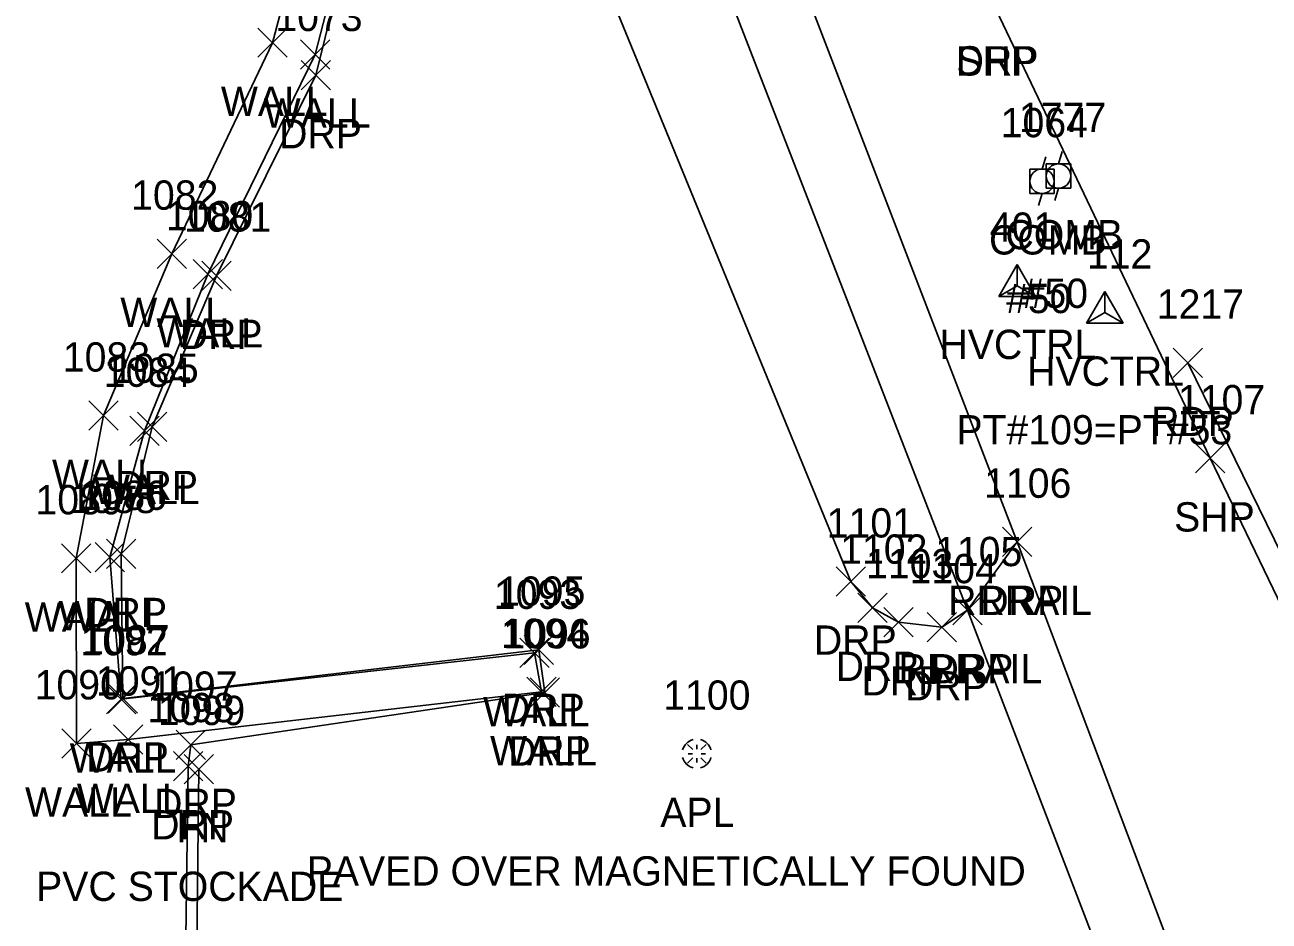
# Model space of a CAD drawing. Extents: x 1635588 to 1637550, y 621583 to 623638.
# Drawn here: x 1636394.7 to 1636479.5, y 623053.3 to 623114.4 of the extents above; entities that cross this region are included whole.
import ezdxf

# ---------------------------------------------------------------- set-up
doc = ezdxf.new("R2010")
doc.units = 0
for name, color, linetype in [('C_A', 7, 'Continuous'), ('C_C', 7, 'Continuous'), ('C_I', 7, 'Continuous'), ('CPSM', 7, 'Continuous'), ('Default', 7, 'Continuous'), ('L_A', 7, 'Continuous'), ('L_C', 7, 'Continuous'), ('L_I', 7, 'Continuous'), ('L_TIC', 7, 'Continuous'), ('LFNC', 7, 'Continuous'), ('LW', 7, 'Continuous'), ('M_A', 7, 'Continuous'), ('M_C', 7, 'Continuous'), ('M_I', 7, 'Continuous'), ('P_A', 7, 'Continuous'), ('P_I', 7, 'Continuous'), ('P_TIC', 7, 'Continuous'), ('PET', 7, 'Continuous'), ('PSP', 7, 'Continuous'), ('R_A', 7, 'Continuous'), ('R_I', 7, 'Continuous'), ('R_TIC', 7, 'Continuous'), ('RDP', 7, 'Continuous'), ('RR', 7, 'Continuous'), ('U_A', 7, 'Continuous'), ('U_C', 7, 'Continuous'), ('U_I', 7, 'Continuous'), ('UP', 7, 'Continuous')]:
    doc.layers.add(name, color=color, linetype=linetype)

msp = doc.modelspace()

# ---------------------------------------------------------------- linework, layer by layer
at = {"layer": 'CPSM'}
for p, q in [((1636461.112, 623095.915), (1636462.362, 623098.081)), ((1636463.612, 623095.915), (1636462.362, 623098.081)), ((1636462.362, 623096.637), (1636462.362, 623098.081)), ((1636461.112, 623095.915), (1636462.362, 623096.637)), ((1636462.362, 623096.637), (1636462.362, 623096.637)), ((1636462.362, 623096.637), (1636463.612, 623095.915)), ((1636467.085, 623094.088), (1636468.335, 623096.253)), ((1636469.585, 623094.088), (1636468.335, 623096.253)), ((1636468.335, 623094.809), (1636468.335, 623096.253)), ((1636461.112, 623095.915), (1636463.612, 623095.915)), ((1636467.085, 623094.088), (1636468.335, 623094.809)), ((1636468.335, 623094.809), (1636468.335, 623094.809)), ((1636468.335, 623094.809), (1636469.585, 623094.088)), ((1636467.085, 623094.088), (1636469.585, 623094.088))]:
    msp.add_line(p, q, dxfattribs=at)
at = {"layer": 'Default'}
for p, q in [((1636439.871, 623065.342), (1636440.225, 623064.989)), ((1636440.508, 623065.006), (1636440.508, 623065.306)), ((1636440.79, 623064.989), (1636441.144, 623065.342)), ((1636439.871, 623064.07), (1636440.225, 623064.423)), ((1636439.908, 623064.706), (1636440.208, 623064.706)), ((1636440.508, 623064.106), (1636440.508, 623064.406)), ((1636440.79, 623064.423), (1636441.144, 623064.07)), ((1636440.808, 623064.706), (1636441.108, 623064.706))]:
    msp.add_line(p, q, dxfattribs=at)
for start, end in [(105, 165), (15, 75), (195, 255), (285, 345)]:
    msp.add_arc((1636440.508, 623064.706), 1, start, end, dxfattribs=at)
at = {"layer": 'L_TIC'}
for points in [[(1636410.564, 623112.225), (1636412.564, 623114.225)], [(1636412.564, 623112.225), (1636410.564, 623114.225)], [(1636413.484, 623111.423), (1636415.484, 623113.423)], [(1636415.484, 623111.423), (1636413.484, 623113.423)], [(1636403.702, 623097.825), (1636405.702, 623099.825)], [(1636405.702, 623097.825), (1636403.702, 623099.825)], [(1636406.16, 623096.425), (1636408.16, 623098.425)], [(1636408.16, 623096.425), (1636406.16, 623098.425)], [(1636399.045, 623086.778), (1636401.045, 623088.778)], [(1636401.045, 623086.778), (1636399.045, 623088.778)], [(1636401.84, 623085.739), (1636403.84, 623087.739)], [(1636403.84, 623085.739), (1636401.84, 623087.739)], [(1636397.187, 623077.038), (1636399.187, 623079.038)], [(1636399.187, 623077.038), (1636397.187, 623079.038)], [(1636399.489, 623077.124), (1636401.489, 623079.124)], [(1636401.489, 623077.124), (1636399.489, 623079.124)], [(1636428.437, 623070.584), (1636430.437, 623072.584)], [(1636430.437, 623070.584), (1636428.437, 623072.584)], [(1636428.919, 623067.918), (1636430.919, 623069.918)], [(1636430.919, 623067.918), (1636428.919, 623069.918)], [(1636428.919, 623067.918), (1636430.919, 623069.918)], [(1636430.919, 623067.918), (1636428.919, 623069.918)], [(1636400.251, 623067.418), (1636402.251, 623069.418)], [(1636402.251, 623067.418), (1636400.251, 623069.418)], [(1636400.736, 623064.668), (1636402.736, 623066.668)], [(1636402.736, 623064.668), (1636400.736, 623066.668)], [(1636397.21, 623064.41), (1636399.21, 623066.41)], [(1636399.21, 623064.41), (1636397.21, 623066.41)], [(1636405.539, 623062.658), (1636407.539, 623064.658)], [(1636407.539, 623062.658), (1636405.539, 623064.658)]]:
    msp.add_lwpolyline(points, dxfattribs=at)
at = {"layer": 'LFNC'}
msp.add_lwpolyline([(1636406.539, 623063.658), (1636405.234, 622947.043)], dxfattribs=at)
at = {"layer": 'LW'}
for points in [[(1636420.537, 623148.867), (1636418.032, 623137.549), (1636411.564, 623113.225), (1636404.702, 623098.825), (1636400.045, 623087.778), (1636398.187, 623078.038), (1636398.21, 623065.41), (1636401.736, 623065.668), (1636429.919, 623068.918)], [(1636420.537, 623148.867), (1636423.272, 623148.269), (1636420.807, 623136.928), (1636414.484, 623112.423), (1636407.16, 623097.425), (1636402.84, 623086.739), (1636400.489, 623078.124), (1636401.251, 623068.418), (1636429.437, 623071.584), (1636429.919, 623068.918)]]:
    msp.add_lwpolyline(points, dxfattribs=at)
at = {"layer": 'P_TIC'}
for points in [[(1636472.997, 623090.384), (1636474.997, 623092.384)], [(1636474.997, 623090.384), (1636472.997, 623092.384)], [(1636474.52, 623083.866), (1636476.52, 623085.866)], [(1636476.52, 623083.866), (1636474.52, 623085.866)]]:
    msp.add_lwpolyline(points, dxfattribs=at)
at = {"layer": 'PET'}
msp.add_lwpolyline([(1636496.543, 623045.303), (1636473.997, 623091.384)], dxfattribs=at)
at = {"layer": 'PSP'}
msp.add_lwpolyline([(1636412.613, 623220.066), (1636436.6, 623167.303), (1636456.229, 623125.071), (1636460.67, 623115.983), (1636475.52, 623084.866), (1636494.511, 623045.421), (1636524.158, 622986.515), (1636530.738, 622972.235), (1636554.067, 622925.303), (1636577.184, 622886.299), (1636601.725, 622847.414), (1636613.464, 622830.092), (1636645.381, 622782.471), (1636700.606, 622698.856), (1636734.281, 622648.07), (1636752.122, 622619.298), (1636752.456, 622616.814), (1636755.34, 622613.417), (1636810.04, 622534.387), (1636855.631, 622465.664), (1636874.755, 622437.489), (1636904.151, 622393.551)], dxfattribs=at)
at = {"layer": 'R_TIC'}
for points in [[(1636413.536, 623110.016), (1636415.536, 623112.016)], [(1636415.536, 623110.016), (1636413.536, 623112.016)], [(1636406.752, 623096.325), (1636408.752, 623098.325)], [(1636408.752, 623096.325), (1636406.752, 623098.325)], [(1636402.358, 623086.008), (1636404.358, 623088.008)], [(1636404.358, 623086.008), (1636402.358, 623088.008)], [(1636461.356, 623078.168), (1636463.356, 623080.168)], [(1636463.356, 623078.168), (1636461.356, 623080.168)], [(1636461.356, 623078.168), (1636463.356, 623080.168)], [(1636463.356, 623078.168), (1636461.356, 623080.168)], [(1636400.247, 623077.342), (1636402.247, 623079.342)], [(1636402.247, 623077.342), (1636400.247, 623079.342)], [(1636450.004, 623075.459), (1636452.004, 623077.459)], [(1636452.004, 623075.459), (1636450.004, 623077.459)], [(1636451.488, 623073.67), (1636453.488, 623075.67)], [(1636453.488, 623073.67), (1636451.488, 623075.67)], [(1636457.958, 623073.504), (1636459.958, 623075.504)], [(1636459.958, 623073.504), (1636457.958, 623075.504)], [(1636457.958, 623073.504), (1636459.958, 623075.504)], [(1636459.958, 623073.504), (1636457.958, 623075.504)], [(1636453.253, 623072.679), (1636455.253, 623074.679)], [(1636455.253, 623072.679), (1636453.253, 623074.679)], [(1636456.222, 623072.339), (1636458.222, 623074.339)], [(1636458.222, 623072.339), (1636456.222, 623074.339)], [(1636428.728, 623070.801), (1636430.728, 623072.801)], [(1636430.728, 623070.801), (1636428.728, 623072.801)], [(1636429.144, 623067.888), (1636431.144, 623069.888)], [(1636431.144, 623067.888), (1636429.144, 623069.888)], [(1636400.371, 623067.481), (1636402.371, 623069.481)], [(1636402.371, 623067.481), (1636400.371, 623069.481)], [(1636405.011, 623064.317), (1636407.011, 623066.317)], [(1636407.011, 623064.317), (1636405.011, 623066.317)], [(1636404.812, 623062.856), (1636406.812, 623064.856)], [(1636406.812, 623062.856), (1636404.812, 623064.856)]]:
    msp.add_lwpolyline(points, dxfattribs=at)
at = {"layer": 'RDP'}
for points in [[(1636426.436, 623136.427), (1636420.977, 623137.097), (1636414.536, 623111.016), (1636407.752, 623097.325), (1636403.358, 623087.008), (1636401.247, 623078.342), (1636401.371, 623068.481), (1636429.728, 623071.801), (1636430.144, 623068.888), (1636406.011, 623065.317), (1636405.812, 623063.856), (1636404.224, 622946.579), (1636428.105, 622945.115), (1636429.145, 622942.892), (1636426.113, 622934.054), (1636419.919, 622924.842), (1636405.506, 622913.035), (1636421.178, 622869.939), (1636453.551, 622783.031), (1636469.62, 622787.524)], [(1636426.436, 623136.427), (1636451.004, 623076.459), (1636452.488, 623074.67), (1636454.253, 623073.679), (1636457.222, 623073.339), (1636458.958, 623074.504), (1636462.356, 623079.168)]]:
    msp.add_lwpolyline(points, dxfattribs=at)
at = {"layer": 'RR'}
for points in [[(1636406.427, 623208.621), (1636424.648, 623171.195), (1636442.267, 623131.473), (1636462.356, 623079.168), (1636475.096, 623045.335), (1636499.502, 622979.797), (1636509.409, 622950.551), (1636516.072, 622929.712), (1636530.199, 622882.108), (1636568.929, 622740.93), (1636580.618, 622697.816)], [(1636401.965, 623205.775), (1636420.488, 623168.355), (1636437.726, 623129.252), (1636458.958, 623074.504), (1636470.759, 623043.725), (1636495.269, 622977.34), (1636504.038, 622950.725), (1636511.183, 622928.714), (1636525.378, 622880.653), (1636564.25, 622739.189), (1636575.997, 622696.585)]]:
    msp.add_lwpolyline(points, dxfattribs=at)
at = {"layer": 'UP'}
for p, q in [((1636465.419, 623105.789), (1636465.169, 623104.956)), ((1636464.297, 623105.436), (1636464.047, 623104.603)), ((1636464.335, 623103.289), (1636464.335, 623104.956)), ((1636464.335, 623104.956), (1636466.002, 623104.956)), ((1636466.002, 623104.956), (1636466.002, 623103.289)), ((1636463.213, 623102.936), (1636463.213, 623104.603)), ((1636463.213, 623104.603), (1636464.88, 623104.603)), ((1636464.88, 623104.603), (1636464.88, 623102.936)), ((1636465.169, 623104.123), (1636465.169, 623104.123)), ((1636464.88, 623102.936), (1636463.213, 623102.936)), ((1636463.797, 623102.103), (1636464.047, 623102.936)), ((1636464.047, 623103.77), (1636464.047, 623103.77)), ((1636466.002, 623103.289), (1636464.335, 623103.289)), ((1636464.919, 623102.456), (1636465.169, 623103.289))]:
    msp.add_line(p, q, dxfattribs=at)
for centre in [(1636465.169, 623104.123), (1636464.047, 623103.77)]:
    msp.add_circle(centre, 0.833, dxfattribs=at)

# ---------------------------------------------------------------- texts
at = {"layer": 'C_A'}
for p in [(1636457.055, 623091.637), (1636463.028, 623089.809)]:
    msp.add_text('HVCTRL', height=2, dxfattribs=at).set_placement(p)
at = {"layer": 'C_C'}
msp.add_text('PT#109=PT#53', height=2, dxfattribs=at).set_placement((1636458.21, 623085.809))
at = {"layer": 'C_I'}
for s, p in [('401', (1636460.488, 623099.637)), ('112', (1636467.107, 623097.809))]:
    msp.add_text(s, height=2, dxfattribs=at).set_placement(p)
at = {"layer": 'L_A'}
for s, p in [('WALL', (1636408.052, 623108.225)), ('WALL', (1636410.972, 623107.423)), ('WALL', (1636401.191, 623093.825)), ('WALL', (1636403.648, 623092.425)), ('WALL', (1636396.534, 623082.778)), ('WALL', (1636399.328, 623081.739)), ('WALL', (1636394.675, 623073.038)), ('WALL', (1636396.977, 623073.124)), ('WALL', (1636425.926, 623066.584)), ('WALL', (1636426.407, 623063.918)), ('WALL', (1636426.407, 623063.918)), ('WALL', (1636397.74, 623063.418)), ('WALL', (1636394.698, 623060.41)), ('WALL', (1636398.225, 623060.668)), ('FN', (1636405.02, 623058.658))]:
    msp.add_text(s, height=2, dxfattribs=at).set_placement(p)
at = {"layer": 'L_C'}
msp.add_text('PVC STOCKADE', height=2, dxfattribs=at).set_placement((1636395.453, 623054.658))
at = {"layer": 'L_I'}
for s, p in [('1082', (1636401.931, 623101.825)), ('1080', (1636404.302, 623100.425)), ('1083', (1636397.274, 623090.778)), ('1084', (1636400.069, 623089.739)), ('1089', (1636395.408, 623081.038)), ('1088', (1636397.717, 623081.124)), ('1093', (1636426.666, 623074.584)), ('1092', (1636398.48, 623071.418)), ('1094', (1636427.147, 623071.918)), ('1094', (1636427.147, 623071.918)), ('1091', (1636399.532, 623068.668)), ('1090', (1636395.352, 623068.41)), ('1099', (1636403.76, 623066.658))]:
    msp.add_text(s, height=2, dxfattribs=at).set_placement(p)
at = {"layer": 'M_A'}
msp.add_text('APL', height=2, dxfattribs=at).set_placement((1636438.019, 623059.706))
at = {"layer": 'M_C'}
msp.add_text('PAVED OVER MAGNETICALLY FOUND', height=2, dxfattribs=at).set_placement((1636413.902, 623055.706))
at = {"layer": 'M_I'}
msp.add_text('1100', height=2, dxfattribs=at).set_placement((1636438.217, 623067.706))
at = {"layer": 'P_A'}
for s, p in [('SHP', (1636458.206, 623110.983)), ('RDP', (1636471.485, 623086.384)), ('SHP', (1636473.055, 623079.866))]:
    msp.add_text(s, height=2, dxfattribs=at).set_placement(p)
at = {"layer": 'P_I'}
for s, p in [('1217', (1636471.871, 623094.384)), ('1107', (1636473.315, 623087.866))]:
    msp.add_text(s, height=2, dxfattribs=at).set_placement(p)
at = {"layer": 'R_A'}
for s, p in [('DRP', (1636458.158, 623110.983)), ('DRP', (1636412.025, 623106.016)), ('DRP', (1636405.241, 623092.325)), ('DRP', (1636400.846, 623082.008)), ('RRRAIL', (1636457.647, 623074.168)), ('DRP', (1636459.844, 623074.168)), ('DRP', (1636398.735, 623073.342)), ('DRP', (1636448.492, 623071.459)), ('DRP', (1636449.976, 623069.67)), ('RRRAIL', (1636454.25, 623069.504)), ('DRP', (1636456.446, 623069.504)), ('DRP', (1636451.741, 623068.679)), ('DRP', (1636454.71, 623068.339)), ('DRP', (1636427.216, 623066.801)), ('DRP', (1636427.632, 623063.888)), ('DRP', (1636398.859, 623063.481)), ('DRP', (1636403.5, 623060.317)), ('DRP', (1636403.301, 623058.856))]:
    msp.add_text(s, height=2, dxfattribs=at).set_placement(p)
at = {"layer": 'R_I'}
for s, p in [('1073', (1636411.765, 623114.016)), ('1081', (1636405.548, 623100.325)), ('1085', (1636400.586, 623090.008)), ('1106', (1636460.096, 623082.168)), ('1106', (1636460.096, 623082.168)), ('1086', (1636398.42, 623081.342)), ('1101', (1636449.366, 623079.459)), ('1102', (1636450.284, 623077.67)), ('1105', (1636456.754, 623077.504)), ('1105', (1636456.754, 623077.504)), ('1103', (1636452.048, 623076.679)), ('1104', (1636455.017, 623076.339)), ('1095', (1636426.957, 623074.801)), ('1087', (1636398.6, 623071.481)), ('1096', (1636427.317, 623071.888)), ('1097', (1636403.24, 623068.317)), ('1098', (1636403.041, 623066.856))]:
    msp.add_text(s, height=2, dxfattribs=at).set_placement(p)
at = {"layer": 'U_A'}
for p in [(1636460.433, 623098.77), (1636461.554, 623099.123)]:
    msp.add_text('COMB', height=2, dxfattribs=at).set_placement(p)
at = {"layer": 'U_C'}
for p in [(1636462.72, 623095.123), (1636461.598, 623094.77)]:
    msp.add_text('#50', height=2, dxfattribs=at).set_placement(p)
at = {"layer": 'U_I'}
for s, p in [('1777', (1636462.476, 623107.123)), ('1064', (1636461.228, 623106.77))]:
    msp.add_text(s, height=2, dxfattribs=at).set_placement(p)

doc.saveas('drawing.dxf')
